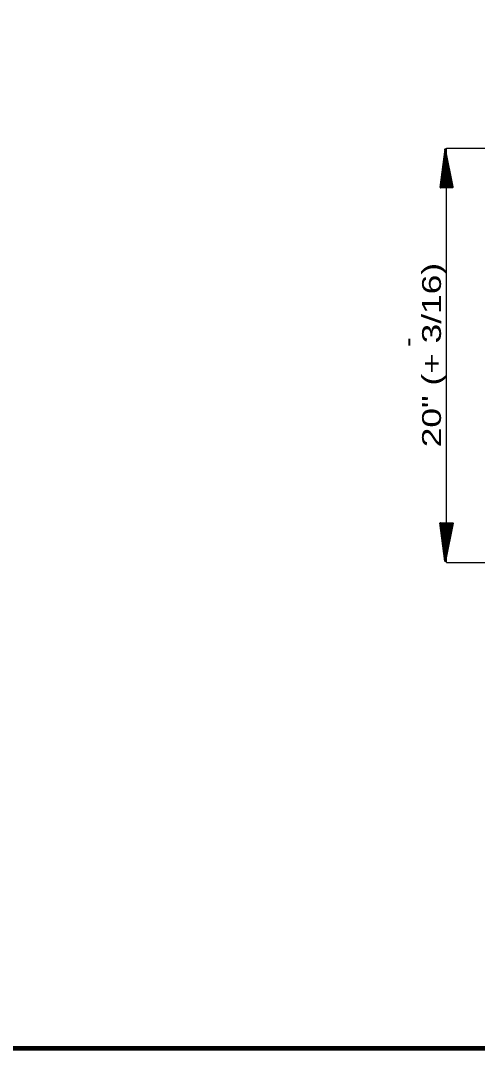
# Model space of a CAD drawing. Extents: x 895.6 to 930.4, y -2278.6 to -2254.7.
# Drawn here: x 911.41 to 914.53, y -2277.16 to -2270.16 of the extents above; entities that cross this region are included whole.
import ezdxf

# ---------------------------------------------------------------- set-up
doc = ezdxf.new("R2010")
doc.units = 0
doc.header["$LTSCALE"] = 0.051
doc.layers.add('1', color=7, linetype='Continuous', lineweight=70)
doc.layers.add('3', color=7, linetype='Continuous', lineweight=40)

msp = doc.modelspace()

# ---------------------------------------------------------------- hatches: boundary and pattern name
at = {"layer": '3'}
for points in [[(914.27733, -2271.29758), (914.364, -2271.29467), (914.31183, -2271.03625), (914.31183, -2271.03625)], [(914.28167, -2271.29633), (914.35967, -2271.29358), (914.31267, -2271.061), (914.31267, -2271.061)], [(914.28558, -2271.29508), (914.35567, -2271.29275), (914.31342, -2271.08342), (914.31342, -2271.08342)], [(914.289, -2271.29408), (914.35208, -2271.29192), (914.31408, -2271.10342), (914.31408, -2271.10342)], [(914.292, -2271.29317), (914.34883, -2271.29125), (914.31467, -2271.1215), (914.31467, -2271.1215)], [(914.29492, -2271.29208), (914.346, -2271.2905), (914.31517, -2271.13775), (914.31517, -2271.13775)], [(914.2975, -2271.29142), (914.34342, -2271.28992), (914.31567, -2271.1525), (914.31567, -2271.1525)], [(914.29967, -2271.29058), (914.34117, -2271.28933), (914.31617, -2271.16575), (914.31617, -2271.16575)], [(914.30167, -2271.29017), (914.33908, -2271.28883), (914.31667, -2271.1775), (914.31667, -2271.1775)], [(914.30367, -2271.28942), (914.33733, -2271.28825), (914.317, -2271.18833), (914.317, -2271.18833)], [(914.30517, -2271.289), (914.3355, -2271.28792), (914.31725, -2271.19792), (914.31725, -2271.19792)], [(914.30675, -2271.2885), (914.33392, -2271.2875), (914.31767, -2271.2065), (914.31767, -2271.2065)], [(914.30808, -2271.28808), (914.33258, -2271.28725), (914.31792, -2271.21442), (914.31792, -2271.21442)], [(914.30933, -2271.2875), (914.33142, -2271.287), (914.31808, -2271.22133), (914.31808, -2271.22133)], [(914.31042, -2271.28733), (914.33025, -2271.28667), (914.31825, -2271.22758), (914.31825, -2271.22758)], [(914.31142, -2271.28692), (914.32925, -2271.2865), (914.31858, -2271.23325), (914.31858, -2271.23325)], [(914.31233, -2271.28675), (914.32842, -2271.28617), (914.31875, -2271.23833), (914.31875, -2271.23833)], [(914.31317, -2271.28658), (914.32758, -2271.286), (914.31892, -2271.24292), (914.31892, -2271.24292)], [(914.31358, -2271.28617), (914.32675, -2271.28592), (914.31892, -2271.247), (914.31892, -2271.247)], [(914.31417, -2271.286), (914.326, -2271.28558), (914.319, -2271.25067), (914.319, -2271.25067)], [(914.31467, -2271.28567), (914.32525, -2271.28525), (914.31883, -2271.25392), (914.31883, -2271.25392)], [(914.31525, -2271.28567), (914.32467, -2271.28525), (914.319, -2271.257), (914.319, -2271.257)], [(914.31575, -2271.2855), (914.32425, -2271.28517), (914.31925, -2271.25975), (914.31925, -2271.25975)], [(914.31617, -2271.28525), (914.32375, -2271.28508), (914.31917, -2271.26208), (914.31917, -2271.26208)], [(914.27733, -2273.58142), (914.364, -2273.58433), (914.31183, -2273.84275), (914.31183, -2273.84275)], [(914.28167, -2273.58267), (914.35967, -2273.58542), (914.31267, -2273.818), (914.31267, -2273.818)], [(914.28558, -2273.58392), (914.35567, -2273.58625), (914.31342, -2273.79558), (914.31342, -2273.79558)], [(914.289, -2273.58492), (914.35208, -2273.58708), (914.31408, -2273.77558), (914.31408, -2273.77558)], [(914.292, -2273.58583), (914.34883, -2273.58775), (914.31467, -2273.7575), (914.31467, -2273.7575)], [(914.29492, -2273.58692), (914.346, -2273.5885), (914.31517, -2273.74125), (914.31517, -2273.74125)], [(914.2975, -2273.58758), (914.34342, -2273.58908), (914.31567, -2273.7265), (914.31567, -2273.7265)], [(914.29967, -2273.58842), (914.34117, -2273.58967), (914.31617, -2273.71325), (914.31617, -2273.71325)], [(914.30167, -2273.58883), (914.33908, -2273.59017), (914.31667, -2273.7015), (914.31667, -2273.7015)], [(914.30367, -2273.58958), (914.33733, -2273.59075), (914.317, -2273.69067), (914.317, -2273.69067)], [(914.30517, -2273.59), (914.3355, -2273.59108), (914.31725, -2273.68108), (914.31725, -2273.68108)], [(914.30675, -2273.5905), (914.33392, -2273.5915), (914.31767, -2273.6725), (914.31767, -2273.6725)], [(914.30808, -2273.59092), (914.33258, -2273.59175), (914.31792, -2273.66458), (914.31792, -2273.66458)], [(914.30933, -2273.5915), (914.33142, -2273.592), (914.31808, -2273.65767), (914.31808, -2273.65767)], [(914.31042, -2273.59167), (914.33025, -2273.59233), (914.31825, -2273.65142), (914.31825, -2273.65142)], [(914.31142, -2273.59208), (914.32925, -2273.5925), (914.31858, -2273.64575), (914.31858, -2273.64575)], [(914.31233, -2273.59225), (914.32842, -2273.59283), (914.31875, -2273.64067), (914.31875, -2273.64067)], [(914.31317, -2273.59242), (914.32758, -2273.593), (914.31892, -2273.63608), (914.31892, -2273.63608)], [(914.31358, -2273.59283), (914.32675, -2273.59308), (914.31892, -2273.632), (914.31892, -2273.632)], [(914.31417, -2273.593), (914.326, -2273.59342), (914.319, -2273.62833), (914.319, -2273.62833)], [(914.31467, -2273.59333), (914.32525, -2273.59375), (914.31883, -2273.62508), (914.31883, -2273.62508)], [(914.31525, -2273.59333), (914.32467, -2273.59375), (914.319, -2273.622), (914.319, -2273.622)], [(914.31575, -2273.5935), (914.32425, -2273.59383), (914.31925, -2273.61925), (914.31925, -2273.61925)], [(914.31617, -2273.59375), (914.32375, -2273.59392), (914.31917, -2273.61692), (914.31917, -2273.61692)]]:
    msp.add_hatch(color=256, dxfattribs=at).paths.add_polyline_path(points)

# ---------------------------------------------------------------- linework, layer by layer
at = {"layer": '1', "lineweight": 25}
for p, q in [((914.31975, -2273.85292), (914.31975, -2271.02867)), ((914.31975, -2271.02867), (915.37317, -2271.02867)), ((914.31975, -2273.85292), (915.37317, -2273.85292))]:
    msp.add_line(p, q, dxfattribs=at)
at = {"layer": '3', "lineweight": 158}
msp.add_lwpolyline([(929.94183, -2256.16333), (929.94183, -2277.16333), (897.44183, -2277.16333)], dxfattribs=at)
at = {"layer": '3'}
for points in [[(914.27733, -2271.29758), (914.364, -2271.29467), (914.31183, -2271.03625), (914.31183, -2271.03625)], [(914.28167, -2271.29633), (914.35967, -2271.29358), (914.31267, -2271.061), (914.31267, -2271.061)], [(914.28558, -2271.29508), (914.35567, -2271.29275), (914.31342, -2271.08342), (914.31342, -2271.08342)], [(914.289, -2271.29408), (914.35208, -2271.29192), (914.31408, -2271.10342), (914.31408, -2271.10342)], [(914.292, -2271.29317), (914.34883, -2271.29125), (914.31467, -2271.1215), (914.31467, -2271.1215)], [(914.29492, -2271.29208), (914.346, -2271.2905), (914.31517, -2271.13775), (914.31517, -2271.13775)], [(914.2975, -2271.29142), (914.34342, -2271.28992), (914.31567, -2271.1525), (914.31567, -2271.1525)], [(914.29967, -2271.29058), (914.34117, -2271.28933), (914.31617, -2271.16575), (914.31617, -2271.16575)], [(914.30167, -2271.29017), (914.33908, -2271.28883), (914.31667, -2271.1775), (914.31667, -2271.1775)], [(914.30367, -2271.28942), (914.33733, -2271.28825), (914.317, -2271.18833), (914.317, -2271.18833)], [(914.30517, -2271.289), (914.3355, -2271.28792), (914.31725, -2271.19792), (914.31725, -2271.19792)], [(914.30675, -2271.2885), (914.33392, -2271.2875), (914.31767, -2271.2065), (914.31767, -2271.2065)], [(914.30808, -2271.28808), (914.33258, -2271.28725), (914.31792, -2271.21442), (914.31792, -2271.21442)], [(914.30933, -2271.2875), (914.33142, -2271.287), (914.31808, -2271.22133), (914.31808, -2271.22133)], [(914.31042, -2271.28733), (914.33025, -2271.28667), (914.31825, -2271.22758), (914.31825, -2271.22758)], [(914.31142, -2271.28692), (914.32925, -2271.2865), (914.31858, -2271.23325), (914.31858, -2271.23325)], [(914.31233, -2271.28675), (914.32842, -2271.28617), (914.31875, -2271.23833), (914.31875, -2271.23833)], [(914.31317, -2271.28658), (914.32758, -2271.286), (914.31892, -2271.24292), (914.31892, -2271.24292)], [(914.31358, -2271.28617), (914.32675, -2271.28592), (914.31892, -2271.247), (914.31892, -2271.247)], [(914.31417, -2271.286), (914.326, -2271.28558), (914.319, -2271.25067), (914.319, -2271.25067)], [(914.31467, -2271.28567), (914.32525, -2271.28525), (914.31883, -2271.25392), (914.31883, -2271.25392)], [(914.31525, -2271.28567), (914.32467, -2271.28525), (914.319, -2271.257), (914.319, -2271.257)], [(914.31575, -2271.2855), (914.32425, -2271.28517), (914.31925, -2271.25975), (914.31925, -2271.25975)], [(914.31617, -2271.28525), (914.32375, -2271.28508), (914.31917, -2271.26208), (914.31917, -2271.26208)], [(914.27733, -2273.58142), (914.364, -2273.58433), (914.31183, -2273.84275), (914.31183, -2273.84275)], [(914.28167, -2273.58267), (914.35967, -2273.58542), (914.31267, -2273.818), (914.31267, -2273.818)], [(914.28558, -2273.58392), (914.35567, -2273.58625), (914.31342, -2273.79558), (914.31342, -2273.79558)], [(914.289, -2273.58492), (914.35208, -2273.58708), (914.31408, -2273.77558), (914.31408, -2273.77558)], [(914.292, -2273.58583), (914.34883, -2273.58775), (914.31467, -2273.7575), (914.31467, -2273.7575)], [(914.29492, -2273.58692), (914.346, -2273.5885), (914.31517, -2273.74125), (914.31517, -2273.74125)], [(914.2975, -2273.58758), (914.34342, -2273.58908), (914.31567, -2273.7265), (914.31567, -2273.7265)], [(914.29967, -2273.58842), (914.34117, -2273.58967), (914.31617, -2273.71325), (914.31617, -2273.71325)], [(914.30167, -2273.58883), (914.33908, -2273.59017), (914.31667, -2273.7015), (914.31667, -2273.7015)], [(914.30367, -2273.58958), (914.33733, -2273.59075), (914.317, -2273.69067), (914.317, -2273.69067)], [(914.30517, -2273.59), (914.3355, -2273.59108), (914.31725, -2273.68108), (914.31725, -2273.68108)], [(914.30675, -2273.5905), (914.33392, -2273.5915), (914.31767, -2273.6725), (914.31767, -2273.6725)], [(914.30808, -2273.59092), (914.33258, -2273.59175), (914.31792, -2273.66458), (914.31792, -2273.66458)], [(914.30933, -2273.5915), (914.33142, -2273.592), (914.31808, -2273.65767), (914.31808, -2273.65767)], [(914.31042, -2273.59167), (914.33025, -2273.59233), (914.31825, -2273.65142), (914.31825, -2273.65142)], [(914.31142, -2273.59208), (914.32925, -2273.5925), (914.31858, -2273.64575), (914.31858, -2273.64575)], [(914.31233, -2273.59225), (914.32842, -2273.59283), (914.31875, -2273.64067), (914.31875, -2273.64067)], [(914.31317, -2273.59242), (914.32758, -2273.593), (914.31892, -2273.63608), (914.31892, -2273.63608)], [(914.31358, -2273.59283), (914.32675, -2273.59308), (914.31892, -2273.632), (914.31892, -2273.632)], [(914.31417, -2273.593), (914.326, -2273.59342), (914.319, -2273.62833), (914.319, -2273.62833)], [(914.31467, -2273.59333), (914.32525, -2273.59375), (914.31883, -2273.62508), (914.31883, -2273.62508)], [(914.31525, -2273.59333), (914.32467, -2273.59375), (914.319, -2273.622), (914.319, -2273.622)], [(914.31575, -2273.5935), (914.32425, -2273.59383), (914.31925, -2273.61925), (914.31925, -2273.61925)], [(914.31617, -2273.59375), (914.32375, -2273.59392), (914.31917, -2273.61692), (914.31917, -2273.61692)]]:
    msp.add_lwpolyline(points, close=True, dxfattribs=at)

# ---------------------------------------------------------------- texts
at = {"layer": '1'}
for s, rotation, width, p in [('20" (+ 3/16)', 90, 1.4, (914.28258, -2273.06733)), ('-', 270, 1.1, (914.01758, -2272.32))]:
    msp.add_text(s, height=0.1286, rotation=rotation, dxfattribs=dict(at, width=width)).set_placement(p)

doc.saveas('drawing.dxf')
